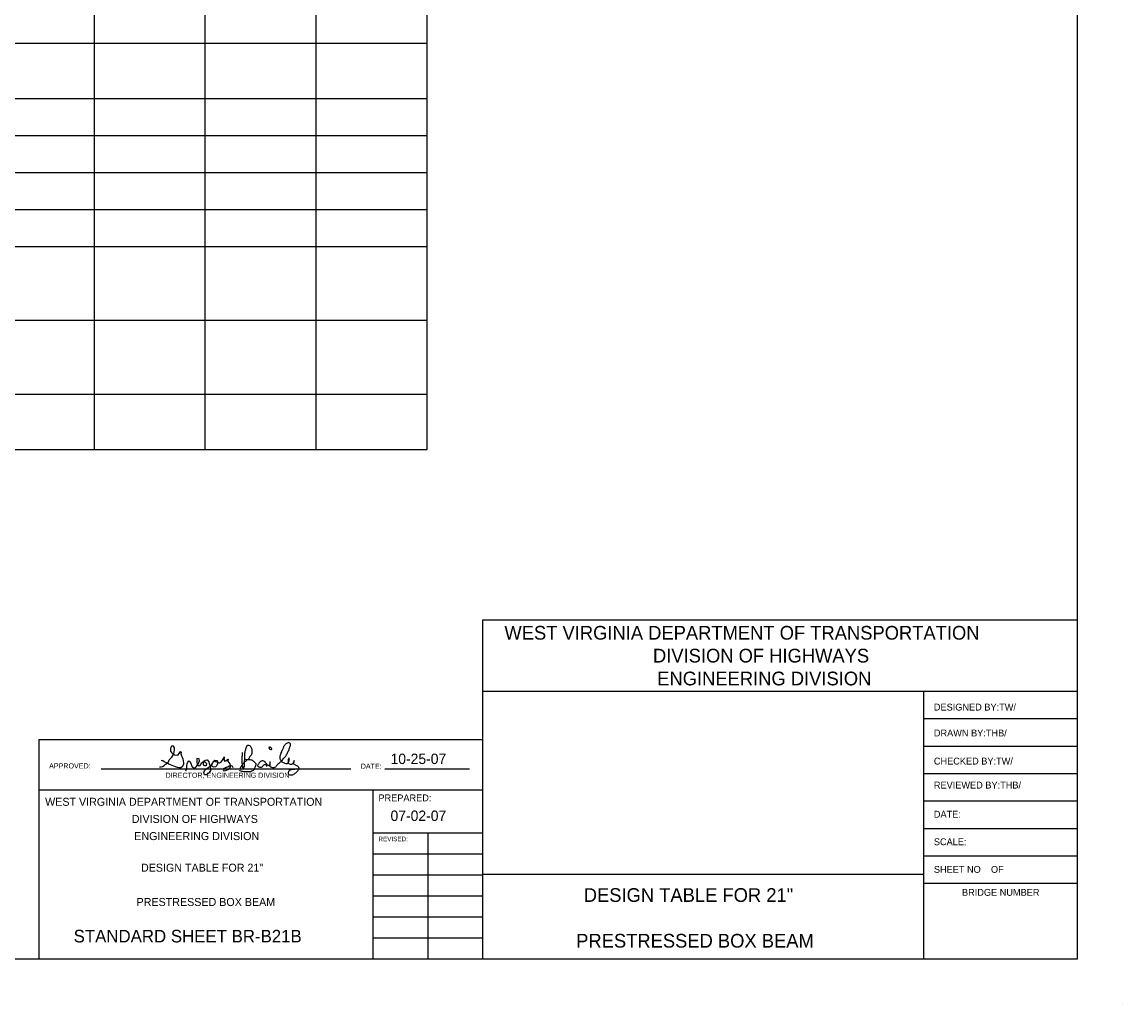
# Model space of a CAD drawing. Extents: x 762.3 to 790.4, y -1210.3 to -1192.2.
# Drawn here: x 780.44 to 790.37, y -1210.35 to -1201.48 of the extents above; entities that cross this region are included whole.
import ezdxf

# ---------------------------------------------------------------- set-up
doc = ezdxf.new("R2010")
doc.units = 0
doc.layers.add('Default', color=7, linetype='Continuous')
doc.layers.add('Level 1', color=7, linetype='Continuous')

msp = doc.modelspace()

# ---------------------------------------------------------------- linework, layer by layer
at = {"layer": 'Default'}
for p, q in [((789.9542, -1192.6096), (789.9542, -1209.9346)), ((784.0909, -1205.3356), (784.0909, -1193.1689)), ((781.0909, -1205.3356), (781.0909, -1193.6689)), ((782.0909, -1205.3356), (782.0909, -1193.6689)), ((783.0909, -1205.3356), (783.0909, -1193.6689)), ((764.5075, -1201.6689), (784.0909, -1201.6689)), ((764.5075, -1202.1689), (784.0909, -1202.1689)), ((766.2575, -1202.5023), (784.0909, -1202.5023)), ((766.2575, -1202.8356), (784.0909, -1202.8356)), ((764.5075, -1203.1689), (784.0909, -1203.1689)), ((766.2575, -1203.5023), (784.0909, -1203.5023)), ((766.2575, -1204.1689), (784.0909, -1204.1689)), ((764.5075, -1204.8356), (784.0909, -1204.8356)), ((764.5075, -1205.3356), (784.0909, -1205.3356)), ((789.9542, -1206.8755), (784.5917, -1206.8755)), ((784.5917, -1206.8755), (784.5917, -1209.9346)), ((788.5682, -1207.519), (784.5917, -1207.519)), ((788.5682, -1207.519), (788.5682, -1209.9346)), ((789.9542, -1207.519), (788.5682, -1207.519)), ((789.9542, -1207.7665), (788.5682, -1207.7665)), ((784.5917, -1207.9546), (780.5905, -1207.9546)), ((780.5905, -1207.9546), (780.5905, -1209.9346)), ((789.9542, -1208.014), (788.5682, -1208.014)), ((781.152, -1208.2157), (783.4022, -1208.2157)), ((783.7105, -1208.2157), (784.4725, -1208.2157)), ((789.9542, -1208.2615), (788.5682, -1208.2615)), ((783.6017, -1208.4083), (780.5905, -1208.4083)), ((783.6017, -1208.4083), (783.6017, -1209.9346)), ((784.5917, -1208.4083), (783.6017, -1208.4083)), ((789.9542, -1208.509), (788.5682, -1208.509)), ((784.5917, -1208.7961), (783.6017, -1208.7961)), ((784.0967, -1208.7961), (784.0967, -1209.9346)), ((789.9542, -1208.7565), (788.5682, -1208.7565)), ((784.5917, -1208.9858), (783.6017, -1208.9858)), ((789.9542, -1209.004), (788.5682, -1209.004)), ((784.5917, -1209.1756), (783.6017, -1209.1756)), ((788.5682, -1209.169), (784.5917, -1209.169)), ((789.9542, -1209.2515), (788.5682, -1209.2515)), ((784.5917, -1209.3653), (783.6017, -1209.3653)), ((784.5917, -1209.5551), (783.6017, -1209.5551)), ((784.5917, -1209.7448), (783.6017, -1209.7448)), ((789.9542, -1209.9346), (763.5542, -1209.9346)), ((790.3667, -1210.3471), (790.3667, -1210.3471))]:
    msp.add_line(p, q, dxfattribs=at)
at = {"layer": 'Level 1'}
for points in [[(781.6772, -1208.1969), (781.6944, -1208.1997), (781.7054, -1208.1943), (781.7201, -1208.1854), (781.7316, -1208.174), (781.7459, -1208.1654), (781.7588, -1208.1525), (781.7659, -1208.1353), (781.7759, -1208.1225), (781.7888, -1208.111), (781.7988, -1208.0967), (781.806, -1208.081), (781.8089, -1208.0624), (781.8117, -1208.0452), (781.8131, -1208.028), (781.8031, -1208.0109), (781.7874, -1208.0109), (781.7788, -1208.0237), (781.7759, -1208.0395), (781.7759, -1208.0567), (781.7874, -1208.0681), (781.7974, -1208.0824), (781.8117, -1208.091), (781.8303, -1208.0924), (781.8461, -1208.0896), (781.8561, -1208.0767), (781.8661, -1208.0609), (781.8747, -1208.0667), (781.8718, -1208.0824), (781.8761, -1208.0981), (781.8818, -1208.1125), (781.8875, -1208.1268), (781.8904, -1208.1439), (781.8933, -1208.1611), (781.8933, -1208.1783), (781.8833, -1208.1969), (781.8718, -1208.2083), (781.8532, -1208.2083), (781.8389, -1208.2044), (781.8217, -1208.1997), (781.8074, -1208.1911), (781.7931, -1208.1875), (781.7774, -1208.1797), (781.7616, -1208.174), (781.7488, -1208.1654), (781.7345, -1208.1597), (781.7201, -1208.1539), (781.7073, -1208.1454), (781.693, -1208.1425)], [(782.4223, -1208.0681), (782.423, -1208.076), (782.423, -1208.0838), (782.423, -1208.0917), (782.423, -1208.1003), (782.4216, -1208.1082), (782.4201, -1208.116), (782.4201, -1208.1239), (782.4201, -1208.1318), (782.4201, -1208.1396), (782.4209, -1208.1475), (782.4216, -1208.1554), (782.4216, -1208.1632), (782.4223, -1208.1711), (782.4237, -1208.179), (782.4244, -1208.1876), (782.4252, -1208.1954), (782.4273, -1208.2033), (782.4323, -1208.209), (782.4366, -1208.2155), (782.4387, -1208.2076), (782.4416, -1208.2004), (782.4438, -1208.1926), (782.4445, -1208.1847), (782.4445, -1208.1768), (782.4445, -1208.169), (782.4452, -1208.1611), (782.4452, -1208.1532), (782.4459, -1208.1454), (782.4466, -1208.1375), (782.4473, -1208.1296), (782.4473, -1208.1218), (782.4473, -1208.1139), (782.4473, -1208.106), (782.4473, -1208.0981), (782.4473, -1208.0903), (782.4473, -1208.0824), (782.448, -1208.0745), (782.4495, -1208.0667), (782.4509, -1208.0581), (782.4531, -1208.0502), (782.4552, -1208.0423), (782.4559, -1208.0345), (782.4588, -1208.0273), (782.4616, -1208.0202), (782.4645, -1208.013), (782.4688, -1208.0059), (782.4759, -1208.003), (782.4838, -1208.0037), (782.4917, -1208.0059), (782.4967, -1208.0116), (782.5003, -1208.0187), (782.5046, -1208.0252), (782.5081, -1208.0323), (782.5096, -1208.0402), (782.5103, -1208.0481), (782.5103, -1208.0559), (782.5103, -1208.0638), (782.5103, -1208.0717), (782.5103, -1208.0795), (782.5089, -1208.0874), (782.5046, -1208.0939), (782.4988, -1208.0989), (782.4938, -1208.1046), (782.491, -1208.1117), (782.4867, -1208.1182), (782.4824, -1208.1246), (782.4795, -1208.1318), (782.4731, -1208.1361), (782.4659, -1208.1396), (782.4595, -1208.1446), (782.4523, -1208.1489), (782.4466, -1208.1539), (782.4409, -1208.1597), (782.4366, -1208.1661), (782.4309, -1208.1711), (782.4266, -1208.1776), (782.4223, -1208.184), (782.4166, -1208.1904), (782.4123, -1208.1969), (782.4094, -1208.204), (782.4051, -1208.2105), (782.4023, -1208.2176), (782.4008, -1208.2255), (782.4037, -1208.2326), (782.4108, -1208.2355), (782.4187, -1208.2362), (782.4266, -1208.2384), (782.4345, -1208.2398), (782.4423, -1208.2405), (782.4502, -1208.2405), (782.4588, -1208.2405), (782.4666, -1208.2405), (782.4745, -1208.2405), (782.4824, -1208.2405), (782.4903, -1208.2405), (782.4981, -1208.2405), (782.506, -1208.2405), (782.5117, -1208.2348), (782.5189, -1208.2319), (782.5253, -1208.2276), (782.5317, -1208.2219), (782.5346, -1208.2148), (782.5375, -1208.2076), (782.5418, -1208.2012), (782.5446, -1208.194), (782.5468, -1208.1861), (782.5482, -1208.1783), (782.5482, -1208.1704), (782.5432, -1208.1647), (782.5375, -1208.1597), (782.5317, -1208.1539), (782.5267, -1208.1475), (782.5196, -1208.1432), (782.5124, -1208.1389), (782.5046, -1208.1375), (782.4967, -1208.1361), (782.4888, -1208.1346), (782.4802, -1208.1346), (782.4717, -1208.1346), (782.4638, -1208.1346), (782.4559, -1208.1332), (782.4559, -1208.1332)], [(782.7821, -1208.1439), (782.7864, -1208.1375), (782.7907, -1208.1311), (782.795, -1208.1246), (782.8, -1208.1189), (782.8065, -1208.1146), (782.8115, -1208.1089), (782.8158, -1208.1017), (782.8193, -1208.0946), (782.8243, -1208.0874), (782.8286, -1208.0803), (782.8315, -1208.0731), (782.8358, -1208.0652), (782.8394, -1208.0574), (782.8429, -1208.0495), (782.8458, -1208.0423), (782.8487, -1208.0352), (782.8515, -1208.028), (782.8537, -1208.0202), (782.8565, -1208.013), (782.858, -1208.0051), (782.8594, -1207.9973), (782.858, -1207.9894), (782.853, -1207.9837), (782.8458, -1207.9808), (782.8379, -1207.9794), (782.8308, -1207.9837), (782.8243, -1207.988), (782.8172, -1207.9908), (782.8115, -1207.9958), (782.8072, -1208.0023), (782.8029, -1208.0087), (782.7972, -1208.0144), (782.7957, -1208.0223), (782.7929, -1208.0295), (782.79, -1208.0366), (782.7857, -1208.0431), (782.7828, -1208.0502), (782.7786, -1208.0567), (782.7771, -1208.0645), (782.7728, -1208.071), (782.7714, -1208.0788), (782.7685, -1208.0867), (782.7657, -1208.0946), (782.7628, -1208.1017), (782.7628, -1208.1096), (782.7628, -1208.1175), (782.7642, -1208.1253), (782.7678, -1208.1325), (782.7707, -1208.1404), (782.7743, -1208.1475), (782.78, -1208.1525), (782.7871, -1208.1554), (782.7936, -1208.1604), (782.8014, -1208.1618), (782.8086, -1208.1661), (782.8158, -1208.169), (782.8243, -1208.1697), (782.8322, -1208.1697), (782.8365, -1208.1632), (782.8408, -1208.1568), (782.8444, -1208.1489), (782.8472, -1208.1411), (782.8479, -1208.1332), (782.8501, -1208.1246), (782.8444, -1208.1196), (782.8415, -1208.1275), (782.8386, -1208.1346), (782.8386, -1208.1425), (782.8386, -1208.1504), (782.8386, -1208.1582), (782.8415, -1208.1661), (782.8487, -1208.1704), (782.8558, -1208.1733), (782.8637, -1208.174), (782.8716, -1208.174), (782.8787, -1208.1711), (782.883, -1208.164), (782.888, -1208.1582), (782.8916, -1208.1504), (782.8937, -1208.1425), (782.8902, -1208.1504), (782.8873, -1208.1575), (782.8844, -1208.1647), (782.8873, -1208.1718), (782.8944, -1208.1754), (782.9016, -1208.179), (782.9066, -1208.1847), (782.9145, -1208.1869), (782.9223, -1208.1897), (782.9274, -1208.1954), (782.9302, -1208.2026), (782.9331, -1208.2097), (782.9331, -1208.2176), (782.9316, -1208.2255), (782.9259, -1208.2305), (782.9216, -1208.2369), (782.9159, -1208.2434), (782.9116, -1208.2498), (782.9045, -1208.2548), (782.8987, -1208.2598), (782.8916, -1208.2641), (782.8844, -1208.2684), (782.878, -1208.2727), (782.8694, -1208.2734), (782.8615, -1208.2741), (782.8537, -1208.2741), (782.8465, -1208.2698), (782.8422, -1208.2634), (782.8408, -1208.2555), (782.8415, -1208.2477), (782.8437, -1208.2398), (782.8479, -1208.2326), (782.853, -1208.2269), (782.8601, -1208.2241), (782.8673, -1208.2212), (782.8751, -1208.2198), (782.883, -1208.2198), (782.8909, -1208.2183), (782.8987, -1208.2183), (782.9066, -1208.2169), (782.9145, -1208.2155), (782.9188, -1208.214)], [(781.9165, -1208.2355), (781.9208, -1208.219), (781.923, -1208.2033), (781.9251, -1208.1876), (781.928, -1208.1718), (781.9337, -1208.1561), (781.943, -1208.1432), (781.9551, -1208.1525), (781.9623, -1208.174), (781.9652, -1208.1897), (781.9752, -1208.2012), (781.9959, -1208.209), (782.0074, -1208.1983), (782.0174, -1208.1854), (782.0267, -1208.1733), (782.0317, -1208.1582), (782.0374, -1208.1432), (782.0353, -1208.1275), (782.0145, -1208.1246), (782.0145, -1208.1404), (782.0145, -1208.1561), (782.0167, -1208.1718), (782.0224, -1208.1869), (782.0403, -1208.1883), (782.0503, -1208.1768), (782.0553, -1208.1611), (782.0696, -1208.1547), (782.0853, -1208.1547), (782.1032, -1208.1683), (782.0982, -1208.1883), (782.0825, -1208.1897), (782.0739, -1208.1768), (782.0746, -1208.1604), (782.0796, -1208.1446), (782.0932, -1208.1375), (782.109, -1208.1346), (782.1218, -1208.1532), (782.1261, -1208.169), (782.1304, -1208.184), (782.1354, -1208.199), (782.1376, -1208.2148), (782.1376, -1208.2312), (782.1261, -1208.2505), (782.114, -1208.2605), (782.1004, -1208.2691), (782.0846, -1208.2698), (782.0782, -1208.2484), (782.0825, -1208.2334), (782.0925, -1208.2219), (782.1035, -1208.2137), (782.1154, -1208.204), (782.1347, -1208.1926), (782.1504, -1208.1761), (782.1559, -1208.1632), (782.1669, -1208.1489), (782.1762, -1208.1368), (782.1969, -1208.1411), (782.2005, -1208.1568), (782.2005, -1208.1725), (782.1948, -1208.1876), (782.1826, -1208.1969), (782.1676, -1208.2019), (782.154, -1208.1947), (782.1512, -1208.1797), (782.1547, -1208.1647), (782.164, -1208.1518), (782.1783, -1208.1461), (782.1991, -1208.1554), (782.2198, -1208.1625), (782.2377, -1208.1511), (782.247, -1208.1389), (782.2549, -1208.1246), (782.2606, -1208.1089), (782.2606, -1208.1167), (782.2592, -1208.1325), (782.2656, -1208.1468), (782.2842, -1208.1418), (782.2942, -1208.1296), (782.2957, -1208.1303), (782.2935, -1208.1461), (782.3021, -1208.1604), (782.3136, -1208.1711), (782.3143, -1208.1869), (782.3143, -1208.2026), (782.3057, -1208.2155), (782.2942, -1208.2262), (782.2792, -1208.2326), (782.2642, -1208.2362), (782.2549, -1208.2241), (782.2649, -1208.2105), (782.2785, -1208.2012), (782.2942, -1208.1983), (782.3071, -1208.1897), (782.3293, -1208.1854), (782.3407, -1208.2033), (782.3422, -1208.2026)], [(782.6677, -1208.0266), (782.6677, -1208.0345), (782.6734, -1208.0395), (782.6813, -1208.0416), (782.6891, -1208.0409), (782.6906, -1208.033), (782.6848, -1208.028), (782.6791, -1208.0223), (782.6712, -1208.0223), (782.6641, -1208.0252), (782.6641, -1208.0302)], [(782.6455, -1208.1962), (782.6469, -1208.1883), (782.6469, -1208.1804), (782.6469, -1208.1725), (782.6405, -1208.1668), (782.6348, -1208.1611), (782.6305, -1208.1547), (782.624, -1208.1504), (782.6176, -1208.1461), (782.6104, -1208.1432), (782.6026, -1208.1432), (782.5947, -1208.1461), (782.589, -1208.1511), (782.5825, -1208.1561), (782.5768, -1208.1611), (782.5725, -1208.1675), (782.5697, -1208.1747), (782.5654, -1208.1811), (782.5625, -1208.1883), (782.5675, -1208.194), (782.5725, -1208.1997), (782.5811, -1208.2019), (782.589, -1208.2019), (782.5968, -1208.2019), (782.604, -1208.199), (782.609, -1208.1926), (782.614, -1208.1869), (782.619, -1208.1804), (782.6262, -1208.1761), (782.6348, -1208.1761), (782.6433, -1208.1768), (782.6505, -1208.1797), (782.6577, -1208.1826), (782.6641, -1208.1869), (782.672, -1208.1869), (782.6741, -1208.179), (782.6763, -1208.1711), (782.677, -1208.1625), (782.677, -1208.1547), (782.6741, -1208.1618), (782.6727, -1208.1697), (782.6727, -1208.1776), (782.6727, -1208.1854), (782.6734, -1208.1933), (782.6805, -1208.1969), (782.6877, -1208.2012), (782.6956, -1208.2033), (782.7034, -1208.204), (782.7113, -1208.204), (782.7192, -1208.2026), (782.7256, -1208.1983), (782.7299, -1208.1911), (782.7356, -1208.1861), (782.7399, -1208.179), (782.7456, -1208.174), (782.7521, -1208.1697), (782.7578, -1208.164), (782.7635, -1208.1582), (782.77, -1208.1539), (782.7764, -1208.1497), (782.7807, -1208.1439)]]:
    msp.add_lwpolyline(points, dxfattribs=at)

# ---------------------------------------------------------------- texts
at = {"layer": 'Default'}
for s, height, p in [('WEST VIRGINIA DEPARTMENT OF TRANSPORTATION', 0.12375, (784.7884, -1207.0508)), ('DIVISION OF HIGHWAYS', 0.12375, (786.1282, -1207.2571)), ('ENGINEERING DIVISION', 0.12375, (786.1667, -1207.4633)), ('DESIGNED BY:TW/', 0.061875, (788.6613, -1207.6904)), ('DRAWN BY:THB/', 0.061875, (788.6613, -1207.9241)), ('10-25-07', 0.09375, (783.7616, -1208.1731)), ('CHECKED BY:TW/', 0.061875, (788.6613, -1208.1776)), ('APPROVED:                                                  ', 0.046406, (780.6826, -1208.2129)), ('DATE:', 0.04641, (783.493, -1208.2157)), ('DIRECTOR, ENGINEERING DIVISION', 0.046406, (781.7318, -1208.2974)), ('REVIEWED BY:THB/', 0.061875, (788.6613, -1208.3941)), ('WEST VIRGINIA DEPARTMENT OF TRANSPORTATION', 0.072188, (780.6464, -1208.5498)), ('PREPARED:', 0.06187, (783.6523, -1208.5093)), ('07-02-07', 0.09375, (783.7616, -1208.6866)), ('DATE:', 0.06187, (788.6613, -1208.6568)), ('DIVISION OF HIGHWAYS', 0.072188, (781.4279, -1208.7045)), ('ENGINEERING DIVISION', 0.072188, (781.4504, -1208.8592)), ('REVISED:', 0.04125, (783.6523, -1208.8696)), ('SCALE:', 0.06187, (788.6613, -1208.9056)), ('DESIGN TABLE FOR 21"', 0.072188, (781.5109, -1209.1444)), ('SHEET NO    OF', 0.061875, (788.6613, -1209.1545)), ('DESIGN TABLE FOR 21"', 0.12375, (785.5039, -1209.4168)), ('BRIDGE NUMBER', 0.061875, (788.9148, -1209.3619)), ('PRESTRESSED BOX BEAM', 0.072188, (781.4711, -1209.4538)), ('STANDARD SHEET BR-B21B', 0.113437, (780.9037, -1209.7825)), ('PRESTRESSED BOX BEAM', 0.12375, (785.4357, -1209.8293))]:
    msp.add_text(s, height=height, dxfattribs=at).set_placement(p)

doc.saveas('drawing.dxf')
